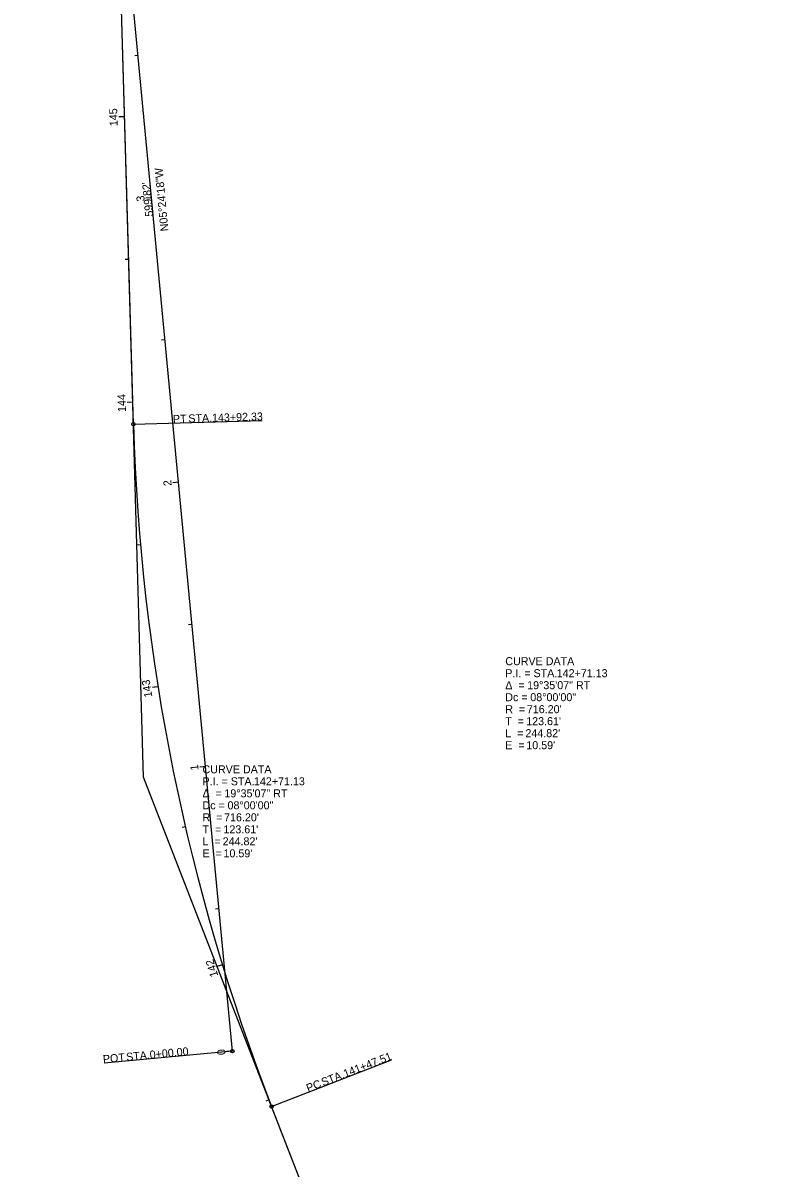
# Model space of a CAD drawing. Extents: x 177110 to 177558, y 286252 to 294117.
# Drawn here: x 177261.2 to 177527.2, y 289867.6 to 290268.4 of the extents above; entities that cross this region are included whole.
import ezdxf

# ---------------------------------------------------------------- set-up
doc = ezdxf.new("R2010")
doc.units = 0
for name, color, linetype in [('GE_X_Alignment', 7, 'Continuous'), ('GE_X_Alignment_100_Bearings', 7, 'Continuous'), ('GE_X_Alignment_100_Cardinal_Points', 7, 'Continuous'), ('GE_X_Alignment_100_Distances', 7, 'Continuous'), ('GE_X_Alignment_100_Stations', 7, 'Continuous'), ('GE_X_Alignment_500_Cardinal_Points', 7, 'Continuous'), ('GE_X_Alignment_500_Curve_Data', 7, 'Continuous'), ('GE_X_Alignment_500_Stations', 7, 'Continuous'), ('RW_X_CL', 7, 'Continuous'), ('RW_X_CL_100_Cardinal_Points', 7, 'Continuous'), ('RW_X_CL_100_Curve_Data', 7, 'Continuous'), ('RW_X_CL_100_Stations', 7, 'Continuous'), ('SC_Scratch1', 7, 'Continuous')]:
    doc.layers.add(name, color=color, linetype=linetype)

msp = doc.modelspace()

# ---------------------------------------------------------------- linework, layer by layer
at = {"layer": 'GE_X_Alignment'}
msp.add_line((177334.49, 289908.55), (177277.99, 290505.7), dxfattribs=at)
at = {"layer": 'GE_X_Alignment_100_Cardinal_Points'}
msp.add_line((177334.49, 289908.55), (177289.69, 289904.31), dxfattribs=at)
msp.add_circle((177334.49, 289908.55), 0.6, dxfattribs=at)
at = {"layer": 'GE_X_Alignment_100_Stations'}
for p, q in [((177301.53, 290257), (177300.33, 290256.88)), ((177306.24, 290207.22), (177304.24, 290207.03)), ((177310.95, 290157.44), (177309.75, 290157.33)), ((177315.65, 290107.66), (177313.66, 290107.48)), ((177320.36, 290057.89), (177319.17, 290057.77)), ((177325.07, 290008.11), (177323.08, 290007.92)), ((177329.78, 289958.33), (177328.59, 289958.22)), ((177334.49, 289908.55), (177332.5, 289908.36))]:
    msp.add_line(p, q, dxfattribs=at)
at = {"layer": 'GE_X_Alignment_500_Cardinal_Points'}
for p, q in [((177299.88, 290127.96), (177344.86, 290129.25)), ((177348.22, 289889.17), (177390.17, 289905.47))]:
    msp.add_line(p, q, dxfattribs=at)
for centre in [(177299.88, 290127.96), (177348.22, 289889.17)]:
    msp.add_circle(centre, 0.6, dxfattribs=at)
at = {"layer": 'GE_X_Alignment_500_Stations'}
for p, q in [((177296.78, 290235.58), (177294.78, 290235.53)), ((177299.66, 290135.62), (177298.46, 290135.59)), ((177308.48, 290036.09), (177307.29, 290035.9)), ((177331.02, 289938.75), (177329.87, 289938.4))]:
    msp.add_line(p, q, dxfattribs=at)
at = {"layer": 'RW_X_CL'}
for p, q in [((177299.88, 290127.96), (177261.21, 291468.79)), ((177516.14, 289457.09), (177348.22, 289889.17))]:
    msp.add_line(p, q, dxfattribs=at)
msp.add_arc((178015.78, 290148.6), 716.2, 181.65191, 201.23721, dxfattribs=at)
at = {"layer": 'RW_X_CL_100_Cardinal_Points'}
for p, q in [((177299.88, 290127.96), (177344.86, 290129.25)), ((177348.22, 289889.17), (177390.17, 289905.47))]:
    msp.add_line(p, q, dxfattribs=at)
for centre in [(177299.88, 290127.96), (177348.22, 289889.17)]:
    msp.add_circle(centre, 0.6, dxfattribs=at)
at = {"layer": 'RW_X_CL_100_Stations'}
for p, q in [((177296.78, 290235.58), (177294.78, 290235.53)), ((177298.22, 290185.6), (177297.02, 290185.57)), ((177299.66, 290135.62), (177297.66, 290135.57)), ((177302.35, 290085.71), (177301.16, 290085.6)), ((177308.48, 290036.09), (177306.5, 290035.78)), ((177318.05, 289987.03), (177316.88, 289986.76)), ((177331.02, 289938.75), (177329.11, 289938.16)), ((177347.32, 289891.49), (177346.2, 289891.06))]:
    msp.add_line(p, q, dxfattribs=at)
at = {"layer": 'SC_Scratch1'}
for p, q in [((177303.45, 290004.39), (177261.21, 291468.79)), ((177527.16, 289428.73), (177303.45, 290004.39))]:
    msp.add_line(p, q, dxfattribs=at)
msp.add_arc((178015.78, 290148.6), 716.2, 181.65191, 201.23721, dxfattribs=at)

# ---------------------------------------------------------------- texts
at = {"layer": 'GE_X_Alignment_100_Bearings'}
msp.add_text('N05°24\'18"W', height=2.8, rotation=95.405, dxfattribs=at).set_placement((177312.16, 290195.6))
at = {"layer": 'GE_X_Alignment_100_Cardinal_Points'}
for s, p in [('POT', (177289.33, 289904.32)), (' STA. ', (177296.42, 289904.99)), ('0+00.00', (177305.7, 289905.87))]:
    msp.add_text(s, height=2.8, rotation=5.405, dxfattribs=at).set_placement(p)
at = {"layer": 'GE_X_Alignment_100_Distances'}
msp.add_text("599.82'", height=2.8, rotation=95.405, dxfattribs=at).set_placement((177306.81, 290200.72))
at = {"layer": 'GE_X_Alignment_100_Stations'}
for s, p in [('3', (177303.84, 290206.02)), ('2', (177313.26, 290106.46)), ('1', (177322.68, 290006.89)), ('0', (177332.1, 289907.29))]:
    msp.add_text(s, height=2.8, rotation=95.405, dxfattribs=at).set_placement(p)
at = {"layer": 'GE_X_Alignment_500_Cardinal_Points'}
for s, rotation, p in [('143+92.33', 1.6519, (177327.4, 290128.79)), ('PT', 1.6519, (177313.73, 290128.39)), (' STA. ', 1.6519, (177318.08, 290128.52)), ('141+47.51', 21.2372, (177373.96, 289899.22)), (' STA. ', 21.2372, (177365.27, 289895.84)), ('PC', 21.2372, (177360.99, 289894.17))]:
    msp.add_text(s, height=2.8, rotation=rotation, dxfattribs=at).set_placement(p)
at = {"layer": 'GE_X_Alignment_500_Curve_Data'}
for s, p in [('CURVE DATA', (177324.05, 290005.77)), ('P.I. = STA. ', (177324.05, 290001.57)), ('142+71.13', (177342.04, 290001.57)), ('Δ  = ', (177324.05, 289997.37)), ('19°35\'07" RT', (177331.7, 289997.37)), ('Dc = ', (177324.05, 289993.17)), ('08°00\'00"', (177332.8, 289993.17)), ('R  = ', (177324.05, 289988.97)), ("716.20'", (177331.59, 289988.97)), ('T  = ', (177324.05, 289984.77)), ("123.61'", (177331.37, 289984.77)), ('L  = ', (177324.05, 289980.57)), ("244.82'", (177331.09, 289980.57)), ('E  = ', (177324.05, 289976.37)), ("10.59'", (177331.39, 289976.37))]:
    msp.add_text(s, height=2.8, dxfattribs=at).set_placement(p)
at = {"layer": 'GE_X_Alignment_500_Stations'}
msp.add_text('145', height=2.8, rotation=91.6519, dxfattribs=at).set_placement((177294.37, 290232.3))
at = {"layer": 'RW_X_CL_100_Cardinal_Points'}
for s, rotation, p in [('143+92.33', 1.6519, (177327.4, 290128.79)), ('PT', 1.6519, (177313.73, 290128.39)), (' STA. ', 1.6519, (177318.08, 290128.52)), ('141+47.51', 21.2372, (177373.96, 289899.22)), (' STA. ', 21.2372, (177365.27, 289895.84)), ('PC', 21.2372, (177360.99, 289894.17))]:
    msp.add_text(s, height=2.8, rotation=rotation, dxfattribs=at).set_placement(p)
at = {"layer": 'RW_X_CL_100_Curve_Data'}
for s, p in [('CURVE DATA', (177429.97, 290043.62)), ('P.I. = STA. ', (177429.97, 290039.42)), ('142+71.13', (177447.96, 290039.42)), ('Δ  = ', (177429.97, 290035.22)), ('19°35\'07" RT', (177437.62, 290035.22)), ('Dc = ', (177429.97, 290031.02)), ('08°00\'00"', (177438.72, 290031.02)), ('R  = ', (177429.97, 290026.82)), ("716.20'", (177437.51, 290026.82)), ('T  = ', (177429.97, 290022.62)), ("123.61'", (177437.29, 290022.62)), ('L  = ', (177429.97, 290018.42)), ("244.82'", (177437.01, 290018.42)), ('E  = ', (177429.97, 290014.22)), ("10.59'", (177437.32, 290014.22))]:
    msp.add_text(s, height=2.8, dxfattribs=at).set_placement(p)
at = {"layer": 'RW_X_CL_100_Stations'}
for s, rotation, p in [('145', 91.6519, (177294.37, 290232.3)), ('144', 91.6519, (177297.26, 290132.27)), ('143', 99.0382, (177306.51, 290032.54)), ('142', 107.0382, (177329.57, 289934.95))]:
    msp.add_text(s, height=2.8, rotation=rotation, dxfattribs=at).set_placement(p)

doc.saveas('drawing.dxf')
